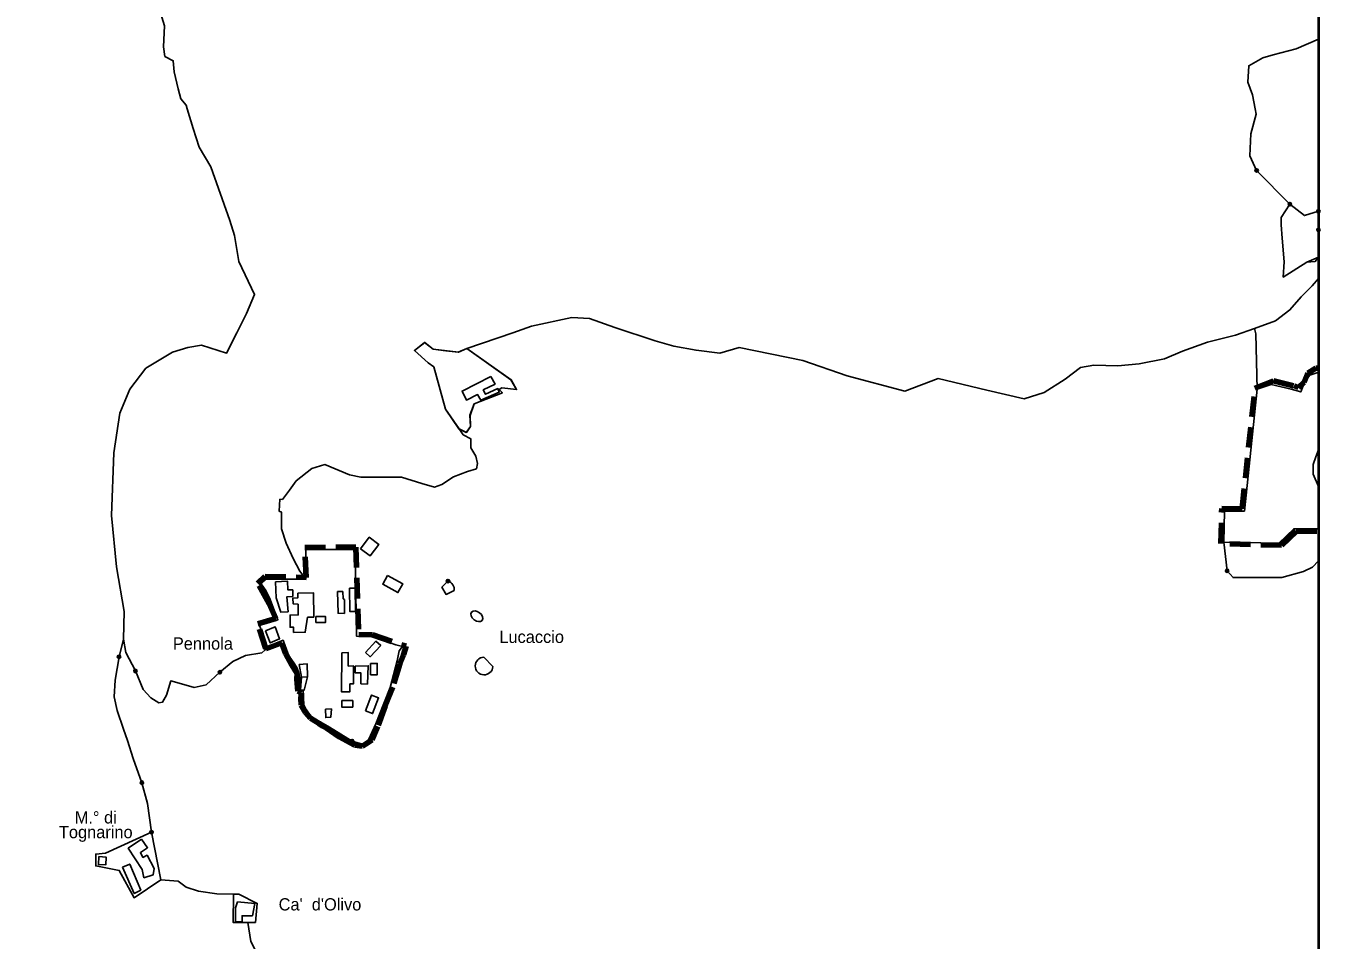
# Model space of a CAD drawing. Extents: x 650071 to 653841, y 889105 to 891996.
# Drawn here: x 652784 to 653841, y 889802 to 890549 of the extents above; entities that cross this region are included whole.
import ezdxf
from ezdxf.enums import TextEntityAlignment as Align

# ---------------------------------------------------------------- set-up
doc = ezdxf.new("R2010")
doc.units = 0
doc.header["$LTSCALE"] = 5.6
doc.header["$PDMODE"] = 32
doc.header["$PDSIZE"] = 2.8
doc.linetypes.add('MEDIUM_DASHED', pattern=[4.5, 3, -1.5])
for name, color, linetype, lineweight in [('1', 7, 'Continuous', 25), ('2', 7, 'Continuous', 25), ('36', 7, 'Continuous', 25), ('37', 7, 'Continuous', 25), ('6', 7, 'Continuous', 25), ('61', 7, 'Continuous', 35), ('7', 7, 'MEDIUM_DASHED', 100), ('8', 7, 'Continuous', 25)]:
    doc.layers.add(name, color=color, linetype=linetype, lineweight=lineweight)
doc.layers.add('60', color=7, linetype='Continuous')

msp = doc.modelspace()

# ---------------------------------------------------------------- linework, layer by layer
at = {"layer": '1'}
for points in [[(652982.98, 890081.36), (652980.16, 890087.26), (652976.19, 890092.71), (652980.22, 890096.62), (653012.82, 890096.63), (653012.83, 890120.75), (653052.97, 890120.75), (653054.18, 890049.94), (653067.59, 890049.37), (653086.25, 890042.83)], [(653133.94, 890087.19), (653127.22, 890084.08), (653123.85, 890089.96), (653128.82, 890095.03)], [(652994.11, 890046.65), (652980.79, 890041.42), (652974.91, 890059.02), (652989.89, 890063.39), (652982.98, 890081.36)], [(653002.79, 890028.19), (652999.16, 890033.55), (652996.35, 890039.64), (652994.11, 890046.65)], [(653086.25, 890042.83), (653091.77, 890041.58), (653088.96, 890038.15), (653087.19, 890029.93), (653081.58, 890008.17), (653076.48, 889995.06), (653069.82, 889978.35), (653065.45, 889968.94), (653062.96, 889963.84), (653058.9, 889961.86), (653054.22, 889963.11), (653050.48, 889964.26), (653032.07, 889975.7), (653026.87, 889978.72), (653023.12, 889980.49)], [(653006.84, 890020.98), (653005.25, 890024.45), (653002.79, 890028.19)], [(653023.12, 889980.49), (653021.04, 889981.43), (653019.11, 889982.82), (653015.71, 889986.26), (653012.36, 889990.96), (653011.02, 889994.01), (653010.5, 890005.55), (653007.67, 890005.8), (653007.94, 890015.94), (653006.84, 890020.98)]]:
    msp.add_lwpolyline(points, dxfattribs=at)
for points in [[(652987.92, 890094.36), (652997.62, 890094.98), (652998, 890087.97), (653002.01, 890087.81), (653002.08, 890082.5), (652997.09, 890082.11), (652998.16, 890069.94), (652992.33, 890069.5), (652988.58, 890081.27)], [(653079.4, 890099.55), (653075.49, 890092.38), (653087.93, 890085.59), (653091.84, 890092.76)], [(653006.06, 890085.24), (653006.07, 890081.24), (653002.17, 890081.11), (653002.39, 890076.29), (653006.41, 890076.05), (653006.46, 890067.4), (652999.86, 890067.17), (652999.86, 890057.33), (653002.55, 890057.39), (653002.68, 890053.04), (653012.28, 890053.16), (653014.18, 890065.5), (653019.11, 890065.55), (653018.99, 890085.32)], [(653038.58, 890086.39), (653042.89, 890086.39), (653043.22, 890080.56), (653044.32, 890079.84), (653044.25, 890068.62), (653039, 890068.68)], [(653048.38, 890089.18), (653052.97, 890089.18), (653053.23, 890070.28), (653048.64, 890070.28)], [(653020.95, 890066.05), (653020.95, 890061.19), (653028.87, 890061.19), (653028.87, 890066.05)], [(652979.81, 890054.34), (652987.78, 890057.59), (652991.32, 890047.84), (652983.65, 890044.44)], [(653061.37, 890036.62), (653065.3, 890033.19), (653073.88, 890042.37), (653069.95, 890045.8)], [(653007.37, 890026.93), (653013.72, 890027.52), (653014.14, 890016.84), (653009.03, 890016.46)], [(653042.06, 890036.47), (653047.31, 890036.54), (653047.31, 890025.62), (653051.74, 890025.68), (653051.6, 890011.01), (653048.73, 890011), (653048.73, 890004.53), (653041.96, 890004.52)], [(653065.65, 890027.8), (653071.06, 890027.8), (653071.06, 890018.51), (653065.65, 890018.51)], [(653009.03, 890016.46), (653008.26, 890006.09), (653011.47, 890005.96), (653014.14, 890016.84)], [(653053.05, 890025.62), (653063.65, 890025.81), (653063.03, 890010.88), (653057.72, 890011.16), (653057.61, 890020.07), (653052.88, 890020.12)], [(653042.02, 889997.34), (653042.02, 889992.02), (653050.99, 889992.02), (653050.99, 889997.34)], [(653061.33, 889989.1), (653067.2, 889986.82), (653072.17, 889999.61), (653066.3, 890001.89)], [(653028.78, 889990.27), (653033.55, 889990.53), (653033.11, 889983.8), (653028.97, 889983.44)]]:
    msp.add_lwpolyline(points, close=True, dxfattribs=at)
msp.add_arc((653126.68, 890088.04), 7.31, 353.29158, 72.9657, dxfattribs=at)
msp.add_ellipse((653152.38, 890066.29), major_axis=(4.32, -3.36), ratio=0.661154, dxfattribs=at)
msp.add_point((653128.82, 890095.03), dxfattribs=at)
at = {"layer": '2'}
msp.add_line((653839.81, 890397.12), (653839.8, 890381.93), dxfattribs=at)
for points in [[(653839.8, 890381.93), (653839.8, 890359.67), (653837.26, 890356.12), (653830.26, 890355.62), (653811.06, 890343.4), (653811.79, 890355.96), (653810.27, 890375.13), (653809.27, 890386.13), (653809.42, 890392.02), (653816.52, 890402.95)], [(653816.52, 890402.95), (653828.35, 890393.66), (653839.81, 890397.12)]]:
    msp.add_lwpolyline(points, dxfattribs=at)
for points in [[(653184.75, 890251.42), (653180.25, 890259.42), (653144.25, 890284.92), (653137.25, 890281.92), (653127, 890283.17), (653116.75, 890284.42), (653113.25, 890287.17), (653109.75, 890289.92), (653101.35, 890283.42), (653112.75, 890273.42), (653117.35, 890269.92), (653126.75, 890235.42), (653137.75, 890219.42), (653143.75, 890216.42), (653147.25, 890221.42), (653146.75, 890230.42), (653150.25, 890239.92), (653173.25, 890248.92), (653170.75, 890251.42), (653172.75, 890252.92)], [(653163.92, 890262.27), (653140.3, 890250.24), (653143.94, 890242.84), (653153.06, 890247.43), (653155.64, 890242.84), (653170.73, 890249.45), (653169.63, 890252.27), (653159.35, 890247.7), (653157.64, 890251.13), (653167.34, 890255.99)], [(652860.35, 889858.64), (652872.45, 889836.3), (652894.15, 889850.82), (652886.65, 889889.82), (652849.15, 889872.67), (652841.16, 889872.03), (652841.15, 889862.32)], [(652878.53, 889884.14), (652867.71, 889876.8), (652878.99, 889859.34), (652880.39, 889852.59), (652888.07, 889855.15), (652888.76, 889860.28), (652883.07, 889870.98), (652879.58, 889869.24), (652877.6, 889873.2), (652883.41, 889877.15)], [(652843.66, 889869.88), (652843.3, 889863.44), (652849.39, 889863.32), (652849.64, 889869.41)], [(652863.06, 889861.25), (652868.88, 889863.81), (652877.83, 889842.51), (652872.6, 889839.77)], [(652953.24, 889816.12), (652971.54, 889816.12), (652973.04, 889831.62), (652958.05, 889839.13), (652953.55, 889839.13)], [(652956.88, 889832.89), (652955.24, 889828.03), (652955.13, 889816.63), (652960.57, 889816.71), (652960.68, 889821.59), (652969.09, 889821.61), (652971.09, 889831.64)]]:
    msp.add_lwpolyline(points, close=True, dxfattribs=at)
for p in [(653839.81, 890397.12), (653839.8, 890381.93)]:
    msp.add_point(p, dxfattribs=at)
at = {"layer": '36'}
for p, q in [((653770.09, 890097.84), (653765.23, 890103.45)), ((652860.13, 890033.18), (652863.65, 890047.63)), ((653050.48, 889964.26), (653032.07, 889975.7))]:
    msp.add_line(p, q, dxfattribs=at)
for points in [[(653789.38, 890430.53), (653783.72, 890442.53), (653784.75, 890460.53), (653788.87, 890476.53), (653788.09, 890480.84), (653786.01, 890492.35), (653782.06, 890502.63), (653782.85, 890516.09), (653794.54, 890522.52), (653802.78, 890525.02), (653821.59, 890529.8), (653839.8, 890537.85), (653839.8, 890691.58)], [(652894.11, 890559.34), (652897.19, 890548.69), (652896.55, 890531.36), (652897.58, 890523.66), (652904.38, 890520.06), (652905.27, 890511.08)], [(652896.55, 890531.36), (652897.19, 890548.69), (652894.11, 890559.34)], [(652908.39, 890497.1), (652905.27, 890511.08), (652904.38, 890520.06), (652897.58, 890523.66), (652896.55, 890531.36)], [(652905.27, 890511.08), (652908.39, 890497.1), (652910.68, 890488.82)], [(652915.88, 890480.84), (652915.02, 890483.73), (652910.53, 890489), (652908.39, 890497.1)], [(652910.68, 890488.82), (652915.02, 890483.73), (652915.88, 890480.84), (652920.67, 890464.74), (652925.68, 890449.46), (652935.17, 890433.41), (652950.63, 890389.72)], [(652925.68, 890449.46), (652920.67, 890464.74), (652915.88, 890480.84)], [(652954.55, 890377.44), (652950.63, 890389.72), (652935.17, 890433.41), (652925.68, 890449.46)], [(653809.42, 890392.02), (653816.52, 890402.95), (653789.38, 890430.53)], [(652950.63, 890389.72), (652954.55, 890377.44), (652958.02, 890356.13), (652970.85, 890329.04), (652964.18, 890313.64), (652956.26, 890297.9), (652947.87, 890281.2), (652927.42, 890287.67)], [(653749.14, 890290.24), (653772.08, 890295.93), (653787.51, 890301.33), (653804.76, 890307.58), (653816.56, 890316.59), (653825.72, 890327.21), (653834.69, 890336.26), (653839.8, 890342.18), (653839.8, 890359.67), (653830.26, 890355.62), (653811.06, 890343.4), (653811.79, 890355.96), (653810.27, 890375.13), (653809.27, 890386.13), (653809.42, 890392.02)], [(652970.85, 890329.04), (652958.02, 890356.13), (652954.55, 890377.44)], [(652956.26, 890297.9), (652964.18, 890313.64), (652970.85, 890329.04)], [(653147.41, 890203.74), (653147.41, 890211.26), (653141.31, 890214.55), (653137.83, 890219.41), (653126.74, 890235.41), (653117.35, 890269.92), (653112.75, 890273.42), (653101.35, 890283.42), (653109.85, 890289.92), (653116.85, 890284.42), (653137.33, 890281.92), (653144.33, 890284.92), (653181.83, 890297.9), (653197.07, 890303.17), (653230.01, 890310.32)], [(653298.14, 890291.37), (653265.12, 890302.27), (653244.4, 890309.65), (653230.01, 890310.32), (653197.07, 890303.17), (653181.83, 890297.9), (653144.33, 890284.92), (653180.31, 890259.42), (653184.8, 890251.42), (653172.81, 890252.92), (653170.71, 890251.42), (653173.31, 890248.92), (653150.33, 890239.91), (653146.83, 890230.41), (653147.33, 890221.41), (653143.83, 890216.41), (653137.83, 890219.41), (653141.31, 890214.55)], [(653230.01, 890310.32), (653244.4, 890309.65), (653265.12, 890302.27), (653298.14, 890291.37), (653313.25, 890286.8), (653331.52, 890283.64), (653350.84, 890281.18), (653366.64, 890285.75), (653418.64, 890275.21), (653454.82, 890262.56)], [(652853.97, 890148.69), (652855.89, 890199.77), (652860.83, 890232.07), (652868.82, 890251.87), (652882.13, 890269), (652903.82, 890281.95), (652916.19, 890285.91), (652927.42, 890287.67), (652947.87, 890281.2), (652956.26, 890297.9)], [(653366.64, 890285.75), (653350.84, 890281.18), (653331.52, 890283.64), (653313.25, 890286.8), (653298.14, 890291.37)], [(653787.52, 890301.33), (653772.08, 890295.93), (653749.14, 890290.24), (653728.72, 890282.81), (653714.05, 890276.62)], [(653765.23, 890103.45), (653762.44, 890126.73), (653763.05, 890152.22), (653779.44, 890152.24), (653789.71, 890251.8), (653788.82, 890297.05), (653787.52, 890301.33)], [(652927.42, 890287.67), (652916.19, 890285.91), (652903.82, 890281.95), (652882.13, 890269)], [(653501.89, 890250.25), (653454.82, 890262.56), (653418.64, 890275.21), (653366.64, 890285.75)], [(653693.32, 890272.4), (653714.05, 890276.62), (653728.72, 890282.81), (653749.14, 890290.24)], [(653676.06, 890270.92), (653656.44, 890271.34), (653645.55, 890269.59), (653632.91, 890260.1), (653615.69, 890249.2), (653599.54, 890243.93)], [(653645.55, 890269.59), (653656.44, 890271.34), (653676.06, 890270.92), (653693.32, 890272.4)], [(653714.05, 890276.62), (653693.32, 890272.4), (653676.06, 890270.92)], [(652882.13, 890269), (652868.82, 890251.87), (652860.83, 890232.07)], [(653454.82, 890262.56), (653501.89, 890250.25), (653529.28, 890260.45), (653568.98, 890250.96), (653599.54, 890243.93), (653615.69, 890249.2)], [(653599.54, 890243.93), (653568.98, 890250.96), (653529.28, 890260.45), (653501.89, 890250.25)], [(653615.69, 890249.2), (653632.91, 890260.1), (653645.55, 890269.59)], [(652860.83, 890232.07), (652855.89, 890199.77), (652853.97, 890148.69), (652858.14, 890106.64)], [(653141.31, 890214.55), (653147.41, 890211.26), (653147.41, 890203.74), (653151.64, 890197.17)], [(653144.75, 890184.42), (653152.1, 890186.83), (653153.04, 890191.06), (653151.64, 890197.17), (653147.41, 890203.74)], [(653151.64, 890197.17), (653153.04, 890191.06), (653152.1, 890186.83), (653144.75, 890184.42)], [(653017.57, 890186.88), (653004.77, 890176.89), (652999.27, 890169.18)], [(653004.77, 890176.89), (653017.57, 890186.88), (653028.26, 890190.2), (653048.29, 890181.72), (653057.74, 890179.78)], [(653117.83, 890171.79), (653107.39, 890174.79), (653090.84, 890179.99), (653057.74, 890179.78), (653048.29, 890181.72), (653028.26, 890190.2), (653017.57, 890186.88)], [(652991.43, 890161.94), (652993.54, 890161.67), (652999.27, 890169.18), (653004.77, 890176.89)], [(653057.74, 890179.78), (653090.84, 890179.99), (653107.39, 890174.79), (653117.83, 890171.79), (653123.76, 890173.82)], [(653144.75, 890184.42), (653133.19, 890180.18), (653123.76, 890173.82), (653117.83, 890171.79)], [(653123.76, 890173.82), (653133.19, 890180.18), (653144.75, 890184.42)], [(652999.27, 890169.18), (652993.54, 890161.67), (652991.43, 890161.94)], [(652991.43, 890161.94), (652990.9, 890152.22), (652992.94, 890151.23), (652992.78, 890137.58)], [(653012.82, 890096.63), (653007.72, 890103.17), (653002.33, 890113.54), (652996.69, 890126.05), (652992.78, 890137.58), (652992.94, 890151.23), (652990.9, 890152.22), (652991.43, 890161.94)], [(652863.65, 890047.63), (652864.31, 890070.06), (652858.14, 890106.64), (652853.97, 890148.69)], [(652992.78, 890137.58), (652996.69, 890126.05), (653002.33, 890113.54), (653007.72, 890103.17), (653012.82, 890096.63), (653012.83, 890120.76), (653052.96, 890120.74), (653054.21, 890049.97), (653067.59, 890049.37), (653086.25, 890042.83), (653091.77, 890041.58), (653088.96, 890038.15), (653087.19, 890029.93), (653081.58, 890008.17), (653076.48, 889995.06), (653069.82, 889978.35), (653065.45, 889968.94), (653062.96, 889963.84), (653058.9, 889961.86), (653050.48, 889964.26)], [(653839.8, 889784.85), (653839.8, 890111.65), (653835.12, 890106.34), (653827.73, 890102.79), (653810.02, 890097.84), (653770.09, 890097.84)], [(652858.14, 890106.64), (652864.31, 890070.06), (652863.65, 890047.63), (652865.76, 890036.71), (652873.51, 890021.56), (652879.85, 890006.4), (652886.19, 889999.71), (652892.52, 889995.48), (652895.69, 889996.19), (652898.86, 890001.82), (652902.38, 890013.45), (652915.06, 890009.93), (652921.4, 890008.17), (652931.26, 890010.28), (652942.53, 890020.5), (652953.09, 890029.31), (652963.3, 890034.24), (652976.68, 890036.36), (652979.15, 890038.47), (652980.79, 890041.42), (652974.91, 890059.02), (652989.89, 890063.39)], [(652989.89, 890063.39), (652984.45, 890077.52), (652980.16, 890087.26), (652976.19, 890092.71), (652980.22, 890096.62), (653012.82, 890096.63)], [(652873.51, 890021.56), (652865.76, 890036.71), (652863.65, 890047.63), (652860.13, 890033.18), (652856.96, 890014.16), (652856.25, 890000.41), (652858.72, 889989.14), (652863.65, 889973.99), (652867.17, 889964.83), (652871.75, 889950.03), (652878.79, 889930.29)], [(653032.07, 889975.7), (653026.87, 889978.72), (653021.04, 889981.43), (653019.11, 889982.82), (653015.71, 889986.26), (653012.36, 889990.96), (653011.02, 889994.01), (653010.5, 890005.55), (653007.67, 890005.8), (653007.94, 890015.94), (653006.84, 890020.98), (653005.25, 890024.45), (652999.16, 890033.55), (652996.35, 890039.64), (652994.11, 890046.65), (652980.79, 890041.42), (652979.15, 890038.47), (652976.68, 890036.36), (652963.3, 890034.24), (652953.09, 890029.31), (652942.53, 890020.5)], [(652939.99, 889839.59), (652924.93, 889841.61), (652914.92, 889845.05), (652908.35, 889849.9), (652894.14, 889850.81), (652872.45, 889836.3), (652860.35, 889858.64), (652841.17, 889862.31), (652841.16, 889872.03), (652849.15, 889872.67), (652886.65, 889889.82), (652883.37, 889913.38), (652878.79, 889930.29), (652871.75, 889950.03), (652867.17, 889964.83), (652863.65, 889973.99), (652858.72, 889989.14), (652856.25, 890000.41), (652856.96, 890014.16), (652860.13, 890033.18)], [(652942.53, 890020.5), (652931.26, 890010.28), (652921.4, 890008.17), (652915.06, 890009.93), (652902.38, 890013.45), (652898.86, 890001.82), (652895.98, 889996.7), (652895.69, 889996.19), (652892.52, 889995.48), (652886.19, 889999.71), (652879.85, 890006.4), (652873.51, 890021.56)], [(652878.79, 889930.29), (652883.37, 889913.38), (652886.65, 889889.82)], [(652886.65, 889889.82), (652894.14, 889850.81), (652908.35, 889849.9), (652914.92, 889845.05)], [(652914.92, 889845.05), (652924.93, 889841.61), (652939.99, 889839.59), (652953.56, 889839.13)], [(652965.37, 889816.12), (652953.24, 889816.12), (652953.56, 889839.13), (652939.99, 889839.59)], [(652953.56, 889839.13), (652958.06, 889839.13), (652973.05, 889831.62), (652971.55, 889816.12), (652965.37, 889816.12)], [(652965.37, 889816.12), (652967.83, 889800.54), (652971.6, 889793.18), (652977.45, 889786.75), (652978.59, 889781.46), (652983.31, 889769.37)], [(652977.45, 889786.75), (652971.6, 889793.18), (652967.83, 889800.54), (652965.37, 889816.12)]]:
    msp.add_lwpolyline(points, dxfattribs=at)
for p in [(653789.38, 890430.53), (653765.23, 890103.45), (652860.13, 890033.18), (652873.51, 890021.56), (652942.53, 890020.5), (653050.48, 889964.26), (652878.79, 889930.29), (652886.65, 889889.82)]:
    msp.add_point(p, dxfattribs=at)
at = {"layer": '37'}
msp.add_line((653789.38, 890430.53), (653816.52, 890402.95), dxfattribs=at)
for points in [[(653816.52, 890402.95), (653828.35, 890393.66), (653839.81, 890397.12), (653839.8, 890537.85), (653821.59, 890529.8), (653802.78, 890525.02), (653794.54, 890522.52), (653782.85, 890516.09), (653782.06, 890502.63), (653786.01, 890492.35), (653788.09, 890480.84), (653788.87, 890476.53), (653784.75, 890460.53), (653783.72, 890442.53), (653789.38, 890430.53)], [(653810.02, 890097.84), (653827.73, 890102.79), (653835.12, 890106.34), (653839.8, 890111.65), (653839.8, 890137.74), (653819.61, 890137.74), (653807.58, 890126.06), (653762.44, 890126.73), (653765.23, 890103.45)], [(653765.23, 890103.45), (653770.09, 890097.84), (653810.02, 890097.84)]]:
    msp.add_lwpolyline(points, dxfattribs=at)
msp.add_lwpolyline([(653817.55, 890251.82), (653825.36, 890249.56), (653828.69, 890257.94), (653832.89, 890263.17), (653838.59, 890265.21), (653839.8, 890265.47), (653839.8, 890342.18), (653834.69, 890336.26), (653825.72, 890327.21), (653816.56, 890316.59), (653804.76, 890307.58), (653787.52, 890301.33), (653788.82, 890297.05), (653789.71, 890251.8), (653801.14, 890255.53)], close=True, dxfattribs=at)
for p in [(653789.38, 890430.53), (653816.52, 890402.95), (653765.23, 890103.45)]:
    msp.add_point(p, dxfattribs=at)
at = {"layer": '6'}
msp.add_line((653158.08, 890032.9), (653165.54, 890025.11), dxfattribs=at)
msp.add_lwpolyline([(653057.36, 890121.32), (653064.5, 890130.84), (653072.26, 890125.02), (653065.13, 890115.5)], close=True, dxfattribs=at)
msp.add_arc((653158.31, 890025.65), 7.25, 91.83572, 355.74233, dxfattribs=at)
at = {"layer": '61', "lineweight": 40}
msp.add_lwpolyline([(653839.81, 891995.66), (653839.8, 889106.04), (652174.44, 889106.04), (652174.45, 891995.66)], close=True, dxfattribs=at)
at = {"layer": '7'}
for points in [[(653838.47, 890135.92), (653821.61, 890135.92), (653809.58, 890124.24), (653760.11, 890125.74), (653760.87, 890154.44), (653777.52, 890154.05), (653787.91, 890252.58), (653803.24, 890258.58), (653819.96, 890254.53), (653823.5, 890253.25), (653828.11, 890257.41), (653831.27, 890264.83), (653837.82, 890269.02), (653839, 890269)], [(652979.57, 890098.7), (653012.86, 890098.06), (653011.96, 890122.36), (653053.6, 890122.82), (653055.9, 890051.31), (653067.05, 890051.08), (653094.57, 890041.79)], [(652993.07, 890044.48), (652980.1, 890039.7), (652973.5, 890059.97), (652988.29, 890064.52), (652982.83, 890076.59), (652973.63, 890093.12), (652979.57, 890098.7)], [(653071.48, 889976.32), (653066.81, 889965.21), (653061.55, 889961.76), (653058.91, 889960.22), (653052.62, 889960.97), (653040.23, 889967.88), (653029.53, 889975.17), (653026.41, 889976.62), (653023.58, 889978.67), (653016.4, 889982.88), (653012.56, 889987.54), (653009.01, 889993.69), (653008.55, 889999.39), (653009.23, 890003.7), (653006.15, 890005.09), (653005.39, 890015.02), (653005.67, 890019.4), (653001.39, 890026.58), (652996.49, 890035.6), (652993.07, 890044.48)], [(653094.57, 890041.79), (653092.59, 890034.75), (653089.37, 890027.45), (653083.83, 890008.42), (653077.57, 889993.15), (653071.48, 889976.32)]]:
    msp.add_lwpolyline(points, dxfattribs=at)
at = {"layer": '8'}
msp.add_lwpolyline([(653839.8, 890172.39), (653839.8, 890137.74), (653819.61, 890137.74), (653807.58, 890126.06), (653762.44, 890126.73), (653763.05, 890152.22), (653779.44, 890152.24), (653789.71, 890251.8), (653801.14, 890255.53), (653817.55, 890251.82), (653825.36, 890249.56), (653828.69, 890257.94), (653832.89, 890263.17), (653838.59, 890265.21), (653839.8, 890265.47), (653839.8, 890202.16), (653837.66, 890196.63), (653835.47, 890190.27), (653835.47, 890182.31)], close=True, dxfattribs=at)

# ---------------------------------------------------------------- texts
at = {"layer": '60'}
for s, p in [('Pennola', (652928.62, 890038.99)), ('Lucaccio', (653197.17, 890044.47)), ('M.° di', (652841.11, 889896.95)), ('Tognarino', (652841.11, 889884.95)), ("Ca'  d'Olivo", (653024.26, 889825.91))]:
    msp.add_text(s, height=10, dxfattribs=at).set_placement(p, align=Align.CENTER)

doc.saveas('drawing.dxf')
